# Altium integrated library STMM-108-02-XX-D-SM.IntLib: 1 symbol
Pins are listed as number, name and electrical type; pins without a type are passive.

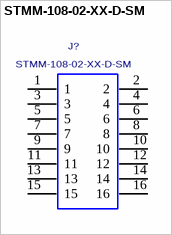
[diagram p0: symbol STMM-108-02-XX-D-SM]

## STMM-108-02-XX-D-SM
designator J?
2 MM TERMINAL STRIP ASSEMBLY, 16 PINS.; MANUFACTURER: SAMTEC
footprint STMM-108-02-XX-D-SM
pins: 1, 2, 3, 4, 5, 6, 7, 8, 9, 10, 11, 12, 13, 14, 15, 16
